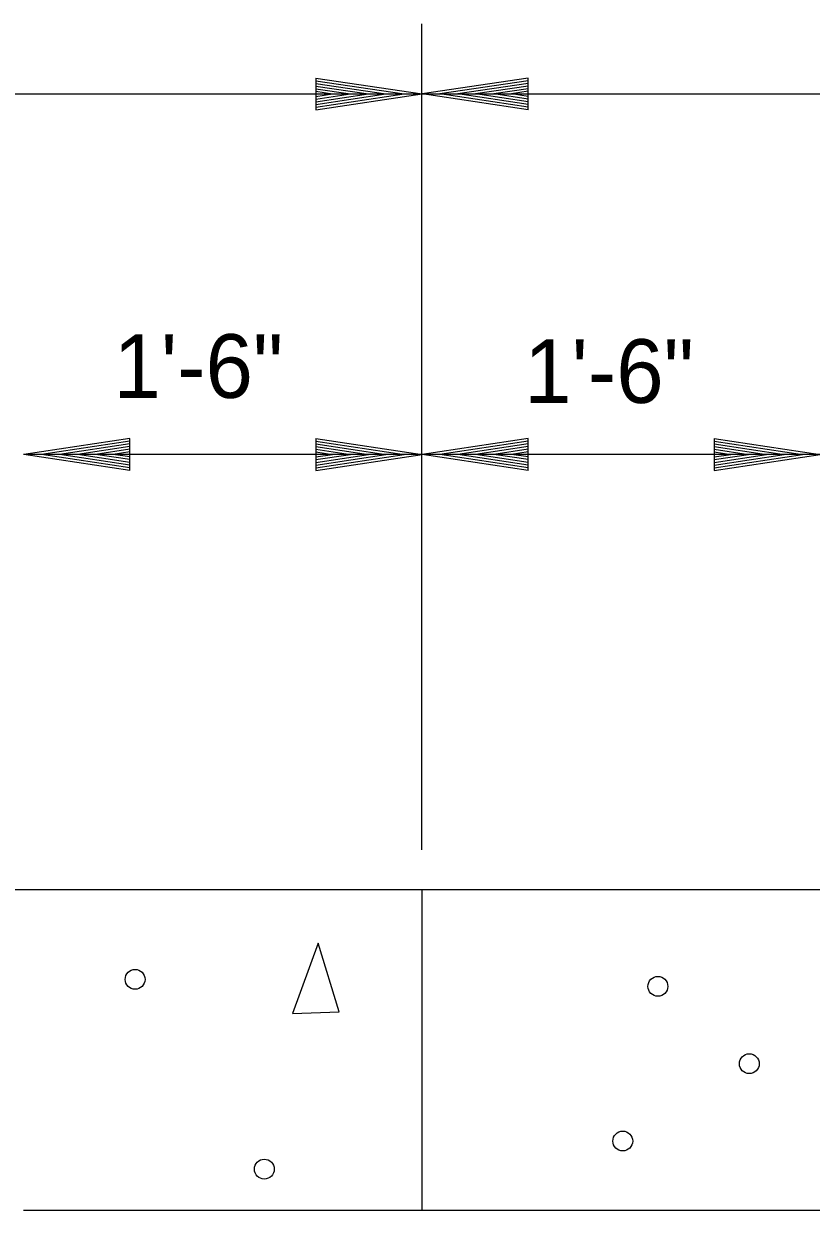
# Model space of a CAD drawing. Extents: x 3287 to 1767681, y -265 to 581440.
# Drawn here: x 3419.01 to 3433.84, y -46.79 to -24.43 of the extents above; entities that cross this region are included whole.
import ezdxf

# ---------------------------------------------------------------- set-up
doc = ezdxf.new("R2010")
doc.units = 0
doc.layers.add('Default', color=7, linetype='Continuous')

msp = doc.modelspace()

# ---------------------------------------------------------------- linework, layer by layer
at = {"layer": 'Default'}
for p, q in [((3426.51, -39.994), (3426.51, -24.434)), ((3424.513, -25.457), (3426.513, -25.757)), ((3424.513, -25.457), (3424.513, -26.057)), ((3428.513, -25.457), (3426.513, -25.757)), ((3428.513, -26.057), (3428.513, -25.457)), ((3424.513, -25.507), (3426.178, -25.757)), ((3424.513, -25.557), (3425.833, -25.757)), ((3424.513, -25.607), (3425.503, -25.757)), ((3424.513, -25.657), (3425.163, -25.757)), ((3428.513, -25.507), (3426.848, -25.757)), ((3428.513, -25.557), (3427.188, -25.757)), ((3428.513, -25.607), (3427.523, -25.757)), ((3428.513, -25.657), (3427.863, -25.757)), ((3326.516, -25.756), (3426.51, -25.756)), ((3424.513, -25.707), (3424.828, -25.757)), ((3424.513, -26.057), (3426.513, -25.757)), ((3424.513, -25.852), (3425.163, -25.757)), ((3424.513, -25.957), (3425.833, -25.757)), ((3424.513, -26.007), (3426.178, -25.757)), ((3424.513, -25.907), (3425.503, -25.757)), ((3424.513, -25.802), (3424.828, -25.757)), ((3426.51, -25.756), (3509.005, -25.756)), ((3428.513, -26.057), (3426.513, -25.757)), ((3428.513, -26.007), (3426.848, -25.757)), ((3428.513, -25.957), (3427.188, -25.757)), ((3428.513, -25.907), (3427.523, -25.757)), ((3428.513, -25.852), (3427.863, -25.757)), ((3428.513, -25.707), (3428.198, -25.757)), ((3428.513, -25.802), (3428.198, -25.757)), ((3421.013, -32.247), (3419.013, -32.547)), ((3421.013, -32.297), (3419.348, -32.547)), ((3421.013, -32.347), (3419.688, -32.547)), ((3421.013, -32.397), (3420.023, -32.547)), ((3421.013, -32.847), (3421.013, -32.247)), ((3424.513, -32.247), (3426.513, -32.547)), ((3424.513, -32.247), (3424.513, -32.847)), ((3424.513, -32.297), (3426.178, -32.547)), ((3424.513, -32.347), (3425.833, -32.547)), ((3424.513, -32.397), (3425.503, -32.547)), ((3428.513, -32.247), (3426.513, -32.547)), ((3428.513, -32.297), (3426.848, -32.547)), ((3428.513, -32.347), (3427.188, -32.547)), ((3428.513, -32.397), (3427.523, -32.547)), ((3428.513, -32.847), (3428.513, -32.247)), ((3432.012, -32.247), (3434.012, -32.547)), ((3432.012, -32.247), (3432.012, -32.847)), ((3432.012, -32.297), (3433.677, -32.547)), ((3432.012, -32.347), (3433.332, -32.547)), ((3432.012, -32.397), (3433.002, -32.547)), ((3426.51, -32.546), (3419.01, -32.546)), ((3421.013, -32.847), (3419.013, -32.547)), ((3421.013, -32.797), (3419.348, -32.547)), ((3421.013, -32.747), (3419.688, -32.547)), ((3421.013, -32.697), (3420.023, -32.547)), ((3421.013, -32.447), (3420.363, -32.547)), ((3421.013, -32.642), (3420.363, -32.547)), ((3421.013, -32.497), (3420.698, -32.547)), ((3421.013, -32.592), (3420.698, -32.547)), ((3424.513, -32.447), (3425.163, -32.547)), ((3424.513, -32.497), (3424.828, -32.547)), ((3424.513, -32.847), (3426.513, -32.547)), ((3424.513, -32.642), (3425.163, -32.547)), ((3424.513, -32.747), (3425.833, -32.547)), ((3424.513, -32.797), (3426.178, -32.547)), ((3424.513, -32.697), (3425.503, -32.547)), ((3424.513, -32.592), (3424.828, -32.547)), ((3434.01, -32.546), (3426.51, -32.546)), ((3428.513, -32.847), (3426.513, -32.547)), ((3428.513, -32.797), (3426.848, -32.547)), ((3428.513, -32.747), (3427.188, -32.547)), ((3428.513, -32.697), (3427.523, -32.547)), ((3428.513, -32.447), (3427.863, -32.547)), ((3428.513, -32.642), (3427.863, -32.547)), ((3428.513, -32.497), (3428.198, -32.547)), ((3428.513, -32.592), (3428.198, -32.547)), ((3432.012, -32.447), (3432.662, -32.547)), ((3432.012, -32.497), (3432.327, -32.547)), ((3432.012, -32.847), (3434.012, -32.547)), ((3432.012, -32.642), (3432.662, -32.547)), ((3432.012, -32.747), (3433.332, -32.547)), ((3432.012, -32.797), (3433.677, -32.547)), ((3432.012, -32.697), (3433.002, -32.547)), ((3432.012, -32.592), (3432.327, -32.547)), ((3326.516, -40.744), (3509.005, -40.744)), ((3426.51, -40.744), (3426.51, -46.785)), ((3419.01, -46.785), (3434.01, -46.785))]:
    msp.add_line(p, q, dxfattribs=at)
msp.add_lwpolyline([(3424.558, -41.756), (3424.073, -43.081), (3424.953, -43.046), (3424.558, -41.756)], dxfattribs=at)
for centre in [(3421.109, -42.435), (3430.955, -42.567), (3432.676, -44.024), (3430.293, -45.481), (3423.543, -46.01)]:
    msp.add_circle(centre, 0.187, dxfattribs=at)

# ---------------------------------------------------------------- texts
for p in [(3420.703, -31.482), (3428.438, -31.577)]:
    msp.add_text('1\'-6"', height=1.2, dxfattribs=at).set_placement(p)

doc.saveas('drawing.dxf')
